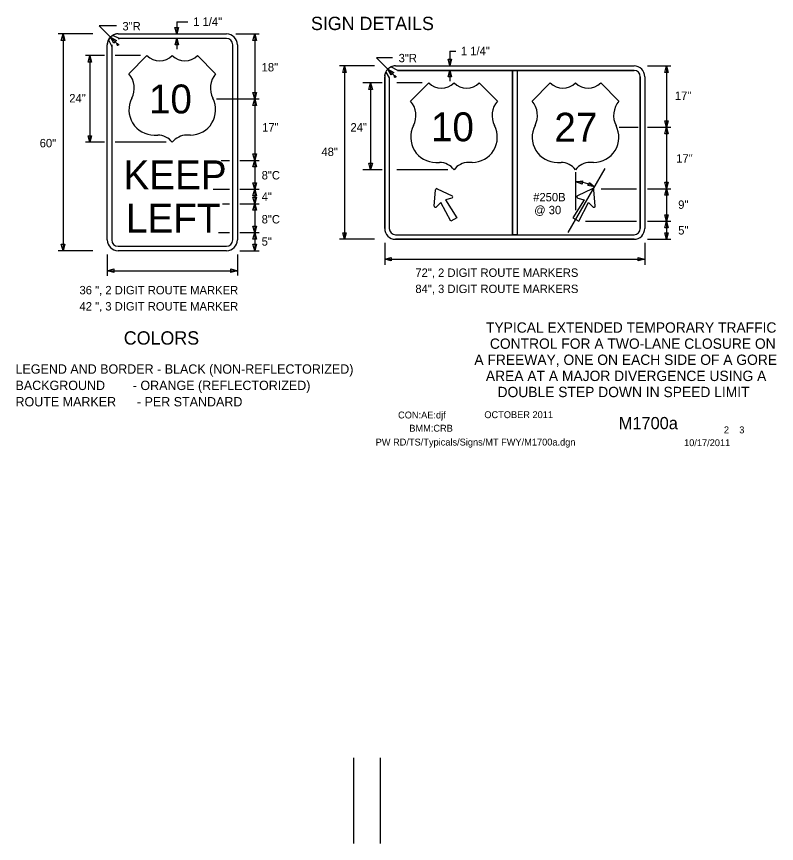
# Model space of a CAD drawing. Extents: x 16486 to 19505, y 5576 to 6998.
# Drawn here: x 17777 to 18460, y 5576 to 6320 of the extents above; entities that cross this region are included whole.
import ezdxf

# ---------------------------------------------------------------- set-up
doc = ezdxf.new("R2010")
doc.units = 0
for name, color, linetype in [('ALI_LEGAL_EX', 7, 'Continuous'), ('BORDER', 7, 'Continuous'), ('BORDER_SIGNAL_WO', 7, 'Continuous'), ('TRAFFIC_SIGNS_PR', 7, 'Continuous'), ('TYPICAL_EX', 7, 'Continuous'), ('TYPICAL_TEXT_DIMEN_PR', 7, 'Continuous')]:
    doc.layers.add(name, color=color, linetype=linetype)

msp = doc.modelspace()

# ---------------------------------------------------------------- linework, layer by layer
at = {"layer": 'ALI_LEGAL_EX'}
for p, q in [((18079.61, 5652.91), (18079.61, 5575.75)), ((18103.61, 5652.91), (18103.61, 5575.75))]:
    msp.add_line(p, q, dxfattribs=at)
at = {"layer": 'TRAFFIC_SIGNS_PR'}
for p, q in [((17860.3, 6300.32), (17859.29, 6298.82)), ((17869.08, 6299.88), (17862.99, 6302.62)), ((17867.88, 6303.94), (17965.38, 6303.94)), ((17858.13, 6118.69), (17858.13, 6294.19)), ((17859.32, 6298.74), (17862.19, 6292.7)), ((17862.19, 6294.19), (17862.19, 6118.69)), ((17965.38, 6299.88), (17867.88, 6299.88)), ((17971.06, 6118.69), (17971.06, 6294.19)), ((17975.13, 6294.19), (17975.13, 6118.69)), ((18119.35, 6271.19), (18113.12, 6274.21)), ((18117.4, 6275.24), (18331.9, 6275.24)), ((18117.4, 6275.24), (18331.9, 6275.24)), ((18119.34, 6271.18), (18222.62, 6271.18)), ((18331.9, 6271.18), (18119.34, 6271.18)), ((18222.62, 6271.18), (18222.62, 6123.31)), ((18226.68, 6271.18), (18226.68, 6123.31)), ((18226.68, 6271.18), (18331.9, 6271.18)), ((18107.65, 6265.49), (18107.65, 6128.99)), ((18107.65, 6128.99), (18107.65, 6265.49)), ((18108.57, 6269.5), (18111.71, 6264.46)), ((18111.71, 6264.44), (18111.71, 6128.99)), ((18111.71, 6264.44), (18111.71, 6128.99)), ((18337.59, 6265.49), (18337.59, 6219.74)), ((18337.59, 6128.99), (18337.59, 6265.49)), ((18341.65, 6265.49), (18341.65, 6128.99)), ((18341.65, 6265.49), (18341.65, 6128.99)), ((18337.59, 6219.74), (18337.59, 6128.99)), ((18152.25, 6149.1), (18153.4, 6163.82)), ((18154.91, 6164.69), (18168.23, 6158.33)), ((18294.38, 6164.69), (18281.07, 6158.33)), ((18297.05, 6149.1), (18295.9, 6163.82)), ((18117.4, 6123.31), (18331.9, 6123.31)), ((18117.4, 6119.24), (18331.9, 6119.24)), ((18331.9, 6119.24), (18117.4, 6119.24)), ((17867.88, 6113), (17965.38, 6113)), ((17965.38, 6108.94), (17867.88, 6108.94))]:
    msp.add_line(p, q, dxfattribs=at)
for points in [[(18119.34, 6271.18), (18119.32, 6271.19)], [(18111.71, 6264.46), (18111.71, 6264.44)], [(18168.07, 6156.36), (18162.34, 6154.78), (18172.56, 6138.61), (18167.16, 6135.49), (18158.27, 6152.43), (18154.04, 6148.26)], [(18281.23, 6156.36), (18286.96, 6154.78), (18276.74, 6138.61), (18282.14, 6135.49), (18291.03, 6152.43), (18295.26, 6148.26)]]:
    msp.add_lwpolyline(points, dxfattribs=at)
msp.add_lwpolyline([(18222.62, 6271.18), (18226.68, 6271.18), (18226.68, 6123.31), (18222.62, 6123.31)], close=True, dxfattribs=at)
for centre, radius, start, end in [((17867.88, 6294.19), 9.75, 90, 180), ((17867.29, 6296.37), 7.6, 85.58319, 124.53531), ((17965.38, 6294.19), 9.75, 0, 90), ((17865.16, 6294.78), 7.06, 145.86811, 184.82317), ((17856.73, 6293.45), 5.51, 352.24294, 7.75653), ((17868.48, 6304.31), 4.47, 262.2432, 277.7568), ((17965.38, 6294.19), 5.69, 0, 90), ((18117.4, 6265.49), 9.75, 90, 180), ((18117.4, 6265.49), 9.75, 90, 180), ((18116.72, 6268.68), 6.6, 84.11162, 123.06374), ((18118.34, 6278.36), 7.24, 277.81035, 278.05403), ((18331.9, 6265.49), 9.75, 0, 90), ((18331.9, 6265.49), 9.75, 0, 90), ((18331.9, 6265.49), 5.69, 0, 89.99421), ((18331.9, 6265.49), 5.69, 0, 90), ((18113.78, 6266.2), 6.17, 147.60925, 186.56283), ((18154.46, 6163.73), 1.06, 64.48226, 175.51774), ((18294.84, 6163.73), 1.06, 4.48226, 115.51774), ((18167.77, 6157.38), 1.06, 285.9885, 64.48226), ((18281.53, 6157.38), 1.06, 115.51774, 254.0115), ((18153.31, 6149.02), 1.06, 175.51775, 314.01151), ((18295.99, 6149.02), 1.06, 225.98849, 4.48225), ((18117.4, 6128.99), 9.75, 180, 270), ((18117.4, 6128.99), 9.75, 180, 270), ((18117.4, 6128.99), 5.69, 180, 270), ((18117.4, 6128.99), 5.69, 180, 270), ((18331.9, 6128.99), 9.75, 270, 0), ((18331.9, 6128.99), 5.69, 270, 0), ((18331.9, 6128.99), 9.75, 270, 0), ((18331.9, 6128.99), 5.69, 270, 0), ((17867.88, 6118.69), 9.75, 180, 270), ((17867.88, 6118.69), 5.69, 180, 270), ((17965.38, 6118.69), 5.69, 270, 0), ((17965.38, 6118.69), 9.75, 270, 0)]:
    msp.add_arc(centre, radius, start, end, dxfattribs=at)
at = {"layer": 'TYPICAL_EX'}
for p, q in [((17877.63, 6268.19), (17893.88, 6284.44)), ((17955.63, 6268.19), (17939.38, 6284.44)), ((18131.01, 6243.58), (18147.26, 6259.83)), ((18209.01, 6243.58), (18192.76, 6259.83)), ((18240.29, 6243.58), (18256.54, 6259.83)), ((18318.29, 6243.58), (18302.04, 6259.83)), ((17900.35, 6212.9), (17903.6, 6212.9)), ((17932.9, 6212.9), (17929.65, 6212.9)), ((18153.74, 6188.29), (18156.99, 6188.29)), ((18186.28, 6188.29), (18183.03, 6188.29)), ((18263.01, 6188.29), (18266.26, 6188.29)), ((18295.56, 6188.29), (18292.31, 6188.29))]:
    msp.add_line(p, q, dxfattribs=at)
for centre, radius, start, end in [((17905.25, 6296.28), 16.42, 226.14041, 313.85958), ((17928, 6296.28), 16.42, 226.14042, 313.85959), ((17862.23, 6255.18), 20.16, 333.09768, 40.19361), ((17971.03, 6255.18), 20.16, 139.80639, 206.90233), ((18158.64, 6271.67), 16.42, 226.14041, 313.85958), ((18181.39, 6271.67), 16.42, 226.14042, 313.85959), ((18267.91, 6271.67), 16.42, 226.14041, 313.85958), ((18290.66, 6271.67), 16.42, 226.14042, 313.85959), ((17900.4, 6235.63), 22.73, 152.6698, 269.90132), ((17932.86, 6235.63), 22.73, 270.09868, 27.3302), ((18115.61, 6230.57), 20.16, 333.09768, 40.19361), ((18224.41, 6230.57), 20.16, 139.80639, 206.90233), ((18224.89, 6230.57), 20.16, 333.09768, 40.19361), ((18333.69, 6230.57), 20.16, 139.80639, 206.90233), ((18153.78, 6211.02), 22.73, 152.6698, 269.90132), ((18186.24, 6211.02), 22.73, 270.09868, 27.3302), ((18263.06, 6211.02), 22.73, 152.6698, 269.90132), ((18295.52, 6211.02), 22.73, 270.09868, 27.3302), ((17903.65, 6196.62), 16.28, 37.1038, 90.13853), ((17929.61, 6196.62), 16.28, 89.86147, 142.8962), ((18157.03, 6172.01), 16.28, 37.1038, 90.13853), ((18182.99, 6172.01), 16.28, 89.86147, 142.8962), ((18266.31, 6172.01), 16.28, 37.1038, 90.13853), ((18292.27, 6172.01), 16.28, 89.86147, 142.8962)]:
    msp.add_arc(centre, radius, start, end, dxfattribs=at)
at = {"layer": 'TYPICAL_TEXT_DIMEN_PR'}
for p, q in [((17866.5, 6311.23), (17850.84, 6311.23)), ((17850.84, 6311.23), (17861.08, 6300.99)), ((17920.6, 6303.94), (17919.03, 6309.8)), ((17919.03, 6309.8), (17920.6, 6309.8)), ((17920.6, 6314.7), (17920.6, 6303.94)), ((17920.6, 6314.7), (17930.71, 6314.7)), ((17920.6, 6309.8), (17922.17, 6309.8)), ((17922.17, 6309.8), (17920.6, 6303.94)), ((17845.3, 6303.94), (17814, 6303.94)), ((17816.77, 6298.08), (17818.34, 6303.94)), ((17818.34, 6303.94), (17818.34, 6108.94)), ((17818.34, 6303.94), (17819.91, 6298.08)), ((17861.08, 6300.99), (17867.64, 6294.43)), ((17864.11, 6295.73), (17861.08, 6300.99)), ((17861.08, 6300.99), (17866.33, 6297.95)), ((17973.67, 6303.94), (17994.63, 6303.94)), ((17989.16, 6298.08), (17990.73, 6303.94)), ((17990.73, 6303.94), (17990.73, 6245.44)), ((17990.73, 6303.94), (17992.3, 6298.08)), ((17818.34, 6298.08), (17816.77, 6298.08)), ((17819.91, 6298.08), (17818.34, 6298.08)), ((17865.22, 6296.84), (17864.11, 6295.73)), ((17866.33, 6297.95), (17865.22, 6296.84)), ((17866.43, 6294.43), (17868.85, 6294.43)), ((17867.64, 6293.22), (17867.64, 6295.64)), ((17919.08, 6294.02), (17920.65, 6299.88)), ((17920.65, 6294.02), (17919.08, 6294.02)), ((17920.65, 6299.88), (17920.65, 6290.13)), ((17920.65, 6299.88), (17922.22, 6294.02)), ((17922.22, 6294.02), (17920.65, 6294.02)), ((17990.73, 6298.08), (17989.16, 6298.08)), ((17992.3, 6298.08), (17990.73, 6298.08)), ((18166.26, 6288.4), (18166.26, 6275.24)), ((18166.26, 6288.4), (18171.78, 6288.4)), ((17855.76, 6284.44), (17838.63, 6284.44)), ((17840.95, 6278.58), (17842.52, 6284.44)), ((17842.52, 6278.58), (17840.95, 6278.58)), ((17842.52, 6284.44), (17842.52, 6206.44)), ((17842.52, 6284.44), (17844.1, 6278.58)), ((17844.1, 6278.58), (17842.52, 6278.58)), ((17887.99, 6284.44), (17865.12, 6284.44)), ((18114.54, 6282.53), (18100.36, 6282.53)), ((18100.36, 6282.53), (18110.51, 6272.38)), ((18166.26, 6275.24), (18164.69, 6281.11)), ((18164.69, 6281.11), (18166.26, 6281.11)), ((18166.26, 6281.11), (18167.83, 6281.11)), ((18167.83, 6281.11), (18166.26, 6275.24)), ((18098.42, 6275.24), (18067.12, 6275.24)), ((18069.89, 6269.38), (18071.46, 6275.24)), ((18071.46, 6275.24), (18071.46, 6119.24)), ((18071.46, 6275.24), (18073.03, 6269.38)), ((18110.51, 6272.38), (18117.16, 6265.73)), ((18113.55, 6267.12), (18110.51, 6272.38)), ((18110.51, 6272.38), (18115.77, 6269.35)), ((18164.74, 6265.32), (18166.31, 6271.18)), ((18164.74, 6265.32), (18166.31, 6271.18)), ((18166.31, 6271.18), (18166.31, 6261.43)), ((18166.31, 6271.18), (18167.88, 6265.32)), ((18166.31, 6271.18), (18167.88, 6265.32)), ((18344.02, 6275.24), (18364.98, 6275.24)), ((18359.51, 6269.38), (18361.08, 6275.24)), ((18361.08, 6275.24), (18361.08, 6219.99)), ((18361.08, 6275.24), (18362.66, 6269.38)), ((18071.46, 6269.38), (18069.89, 6269.38)), ((18073.03, 6269.38), (18071.46, 6269.38)), ((18114.66, 6268.23), (18113.55, 6267.12)), ((18115.77, 6269.35), (18114.66, 6268.23)), ((18115.95, 6265.73), (18118.37, 6265.73)), ((18117.16, 6264.53), (18117.16, 6266.94)), ((18166.31, 6265.32), (18164.74, 6265.32)), ((18166.31, 6265.32), (18164.74, 6265.32)), ((18167.88, 6265.32), (18166.31, 6265.32)), ((18167.88, 6265.32), (18166.31, 6265.32)), ((18361.08, 6269.38), (18359.51, 6269.38)), ((18362.66, 6269.38), (18361.08, 6269.38)), ((18105.28, 6259.83), (18088.15, 6259.83)), ((18093.45, 6253.97), (18095.02, 6259.83)), ((18095.02, 6259.83), (18095.02, 6181.83)), ((18095.02, 6259.83), (18096.59, 6253.97)), ((18141.38, 6259.83), (18118.5, 6259.83)), ((17990.73, 6245.44), (17989.16, 6251.3)), ((17989.16, 6251.3), (17990.73, 6251.3)), ((17990.73, 6251.3), (17992.3, 6251.3)), ((17992.3, 6251.3), (17990.73, 6245.44)), ((18095.02, 6253.97), (18093.45, 6253.97)), ((18096.59, 6253.97), (18095.02, 6253.97)), ((17956.52, 6245.44), (17994.63, 6245.44)), ((17989.16, 6239.58), (17990.73, 6245.44)), ((17990.73, 6245.44), (17990.73, 6190.19)), ((17990.73, 6245.44), (17992.3, 6239.58)), ((17990.73, 6239.58), (17989.16, 6239.58)), ((17992.3, 6239.58), (17990.73, 6239.58)), ((18318.46, 6219.99), (18335.62, 6219.99)), ((18344.02, 6219.99), (18364.98, 6219.99)), ((18361.08, 6219.99), (18359.51, 6225.86)), ((18359.51, 6225.86), (18361.08, 6225.86)), ((18359.51, 6214.13), (18361.08, 6219.99)), ((18361.08, 6225.86), (18362.66, 6225.86)), ((18362.66, 6225.86), (18361.08, 6219.99)), ((18361.08, 6219.99), (18361.08, 6164.74)), ((18361.08, 6219.99), (18362.66, 6214.13)), ((17842.52, 6206.44), (17840.95, 6212.3)), ((17840.95, 6212.3), (17842.52, 6212.3)), ((17842.52, 6212.3), (17844.1, 6212.3)), ((17844.1, 6212.3), (17842.52, 6206.44)), ((18361.08, 6214.13), (18359.51, 6214.13)), ((18362.66, 6214.13), (18361.08, 6214.13)), ((17855.76, 6206.44), (17838.63, 6206.44)), ((17911.12, 6206.44), (17865.12, 6206.44)), ((17960.46, 6190.19), (17968.14, 6190.19)), ((17977.5, 6190.19), (17994.63, 6190.19)), ((17990.73, 6190.19), (17989.16, 6196.05)), ((17989.16, 6196.05), (17990.73, 6196.05)), ((17989.16, 6184.33), (17990.73, 6190.19)), ((17990.73, 6196.05), (17992.3, 6196.05)), ((17992.3, 6196.05), (17990.73, 6190.19)), ((17990.73, 6190.19), (17990.73, 6164.19)), ((17990.73, 6190.19), (17992.3, 6184.33)), ((17990.73, 6184.33), (17989.16, 6184.33)), ((17992.3, 6184.33), (17990.73, 6184.33)), ((18105.28, 6181.83), (18088.15, 6181.83)), ((18095.02, 6181.83), (18093.45, 6187.69)), ((18093.45, 6187.69), (18095.02, 6187.69)), ((18095.02, 6187.69), (18096.59, 6187.69)), ((18096.59, 6187.69), (18095.02, 6181.83)), ((18164.5, 6181.83), (18118.5, 6181.83)), ((18272.68, 6125.34), (18305.92, 6182.93)), ((18279.44, 6145.5), (18279.44, 6179.49)), ((17990.73, 6164.19), (17989.16, 6170.05)), ((17989.16, 6170.05), (17990.73, 6170.05)), ((17990.73, 6170.05), (17992.3, 6170.05)), ((17992.3, 6170.05), (17990.73, 6164.19)), ((18279.47, 6170.94), (18285.46, 6171.9)), ((18285.14, 6168.77), (18279.47, 6170.94)), ((18285.3, 6170.33), (18285.14, 6168.77)), ((18285.46, 6171.9), (18285.3, 6170.33)), ((18290.45, 6167.61), (18291.14, 6169.03)), ((18296.42, 6166.48), (18290.45, 6167.61)), ((18291.14, 6169.03), (18291.82, 6170.44)), ((18291.82, 6170.44), (18296.42, 6166.48)), ((18361.08, 6164.74), (18359.51, 6170.61)), ((18359.51, 6170.61), (18361.08, 6170.61)), ((18361.08, 6170.61), (18362.66, 6170.61)), ((18362.66, 6170.61), (18361.08, 6164.74)), ((17953.44, 6164.19), (17968.14, 6164.19)), ((17977.5, 6164.19), (17994.63, 6164.19)), ((17989.16, 6158.33), (17990.73, 6164.19)), ((17990.73, 6164.19), (17990.73, 6151.19)), ((17990.73, 6164.19), (17992.3, 6158.33)), ((18302.39, 6164.74), (18334.26, 6164.74)), ((18344.02, 6164.74), (18364.98, 6164.74)), ((18359.51, 6158.88), (18361.08, 6164.74)), ((18361.08, 6164.74), (18361.08, 6135.49)), ((18361.08, 6164.74), (18362.66, 6158.88)), ((17990.73, 6158.33), (17989.16, 6158.33)), ((17990.73, 6151.19), (17989.16, 6157.05)), ((17989.16, 6157.05), (17990.73, 6157.05)), ((17992.3, 6158.33), (17990.73, 6158.33)), ((17990.73, 6157.05), (17992.3, 6157.05)), ((17992.3, 6157.05), (17990.73, 6151.19)), ((18361.08, 6158.88), (18359.51, 6158.88)), ((18362.66, 6158.88), (18361.08, 6158.88)), ((17961.79, 6151.19), (17968.14, 6151.19)), ((17977.5, 6151.19), (17994.63, 6151.19)), ((17989.16, 6145.33), (17990.73, 6151.19)), ((17990.73, 6145.33), (17989.16, 6145.33)), ((17990.73, 6151.19), (17990.73, 6125.19)), ((17990.73, 6151.19), (17992.3, 6145.33)), ((17992.3, 6145.33), (17990.73, 6145.33)), ((18361.08, 6135.49), (18359.51, 6141.36)), ((18359.51, 6141.36), (18361.08, 6141.36)), ((18361.08, 6141.36), (18362.66, 6141.36)), ((18362.66, 6141.36), (18361.08, 6135.49)), ((17990.73, 6125.19), (17989.16, 6131.05)), ((17989.16, 6131.05), (17990.73, 6131.05)), ((17990.73, 6131.05), (17992.3, 6131.05)), ((17992.3, 6131.05), (17990.73, 6125.19)), ((18288.26, 6135.49), (18334.26, 6135.49)), ((18344.02, 6135.49), (18364.98, 6135.49)), ((18359.51, 6129.63), (18361.08, 6135.49)), ((18361.08, 6129.63), (18359.51, 6129.63)), ((18361.08, 6135.49), (18361.08, 6119.24)), ((18361.08, 6135.49), (18362.66, 6129.63)), ((18362.66, 6129.63), (18361.08, 6129.63)), ((17958.29, 6125.19), (17968.14, 6125.19)), ((17977.5, 6125.19), (17994.63, 6125.19)), ((17989.16, 6119.33), (17990.73, 6125.19)), ((17990.73, 6125.19), (17990.73, 6108.94)), ((17990.73, 6125.19), (17992.3, 6119.33)), ((18071.46, 6119.24), (18069.89, 6125.11)), ((18069.89, 6125.11), (18071.46, 6125.11)), ((18071.46, 6125.11), (18073.03, 6125.11)), ((18073.03, 6125.11), (18071.46, 6119.24)), ((18361.08, 6119.24), (18359.51, 6125.11)), ((18359.51, 6125.11), (18361.08, 6125.11)), ((18361.08, 6125.11), (18362.66, 6125.11)), ((18362.66, 6125.11), (18361.08, 6119.24)), ((17818.34, 6108.94), (17816.77, 6114.8)), ((17816.77, 6114.8), (17818.34, 6114.8)), ((17818.34, 6114.8), (17819.91, 6114.8)), ((17819.91, 6114.8), (17818.34, 6108.94)), ((17990.73, 6119.33), (17989.16, 6119.33)), ((17990.73, 6108.94), (17989.16, 6114.8)), ((17989.16, 6114.8), (17990.73, 6114.8)), ((17992.3, 6119.33), (17990.73, 6119.33)), ((17990.73, 6114.8), (17992.3, 6114.8)), ((17992.3, 6114.8), (17990.73, 6108.94)), ((18098.42, 6119.24), (18067.12, 6119.24)), ((18107.65, 6115.9), (18107.65, 6096.34)), ((18341.65, 6115.9), (18341.65, 6096.34)), ((18344.02, 6119.24), (18361.15, 6119.24)), ((18344.02, 6119.24), (18364.98, 6119.24)), ((18344.02, 6119.24), (18361.15, 6119.24)), ((17845.3, 6108.94), (17814, 6108.94)), ((17977.5, 6108.94), (17994.63, 6108.94)), ((17858.13, 6105.6), (17858.13, 6086.24)), ((17975.13, 6105.6), (17975.13, 6086.7)), ((18107.65, 6101.27), (18113.51, 6102.84)), ((18107.65, 6101.27), (18341.65, 6101.27)), ((18113.51, 6099.7), (18107.65, 6101.27)), ((18113.51, 6102.84), (18113.51, 6101.27)), ((18113.51, 6101.27), (18113.51, 6099.7)), ((18335.79, 6101.27), (18335.79, 6102.84)), ((18335.79, 6102.84), (18341.65, 6101.27)), ((18341.65, 6101.27), (18335.79, 6099.7)), ((18335.79, 6099.7), (18335.79, 6101.27)), ((17858.13, 6090.97), (17863.99, 6092.54)), ((17863.99, 6092.54), (17863.99, 6090.97)), ((17969.27, 6090.97), (17969.27, 6092.54)), ((17969.27, 6092.54), (17975.13, 6090.97)), ((17858.13, 6090.97), (17975.13, 6090.97)), ((17863.99, 6089.4), (17858.13, 6090.97)), ((17863.99, 6090.97), (17863.99, 6089.4)), ((17975.13, 6090.97), (17969.27, 6089.4)), ((17969.27, 6089.4), (17969.27, 6090.97))]:
    msp.add_line(p, q, dxfattribs=at)
msp.add_arc((18279.63, 6136.5), 34.39, 60.74521, 90.32117, dxfattribs=at)

# ---------------------------------------------------------------- texts
at = {"layer": 'BORDER'}
for s, p in [('TYPICAL EXTENDED TEMPORARY TRAFFIC', (18198.79, 6035.19)), ('CONTROL FOR A TWO-LANE CLOSURE ON', (18202.28, 6020.7)), ('A FREEWAY, ONE ON EACH SIDE OF A GORE', (18188.3, 6006.21)), ('AREA AT A MAJOR DIVERGENCE USING A', (18198.66, 5991.71)), ('DOUBLE STEP DOWN IN SPEED LIMIT', (18209.16, 5977.22))]:
    msp.add_text(s, height=9.3, dxfattribs=at).set_placement(p)
at = {"layer": 'BORDER_SIGNAL_WO'}
for s, height, p in [('CON:AE:djf  ', 6.2, (18119.69, 5958.06)), ('    OCTOBER 2011', 6.2, (18188.08, 5958.34)), ('    M1700a   ', 11, (18301.86, 5948.38)), ('BMM:CRB', 6.2, (18129.81, 5946.17)), (' 2    3 ', 6.2, (18410.45, 5944.7)), ('PW RD/TS/Typicals/Signs/MT FWY/M1700a.dgn      ', 6.2, (18099.55, 5933.71)), ('10/17/2011', 6.2, (18376.93, 5933.13))]:
    msp.add_text(s, height=height, dxfattribs=at).set_placement(p)
at = {"layer": 'TRAFFIC_SIGNS_PR'}
for s, p in [('10', (17895.6, 6232.44)), ('10', (18149.25, 6207.37)), ('27', (18260.26, 6207.01)), ('KEEP', (17872.73, 6164.19)), ('LEFT', (17874.97, 6125.19))]:
    msp.add_text(s, height=26, dxfattribs=at).set_placement(p)
at = {"layer": 'TYPICAL_TEXT_DIMEN_PR'}
for s, height, p in [('1 1/4"', 7.55, (17935.4, 6311.2)), ('SIGN DETAILS', 12, (18041.35, 6307.41)), ('3"R', 7.55, (17871.77, 6307.1)), ('3"R', 7.55, (18120.18, 6278.45)), ('1 1/4"', 7.55, (18176.18, 6284.82)), ('18"', 7.55, (17996.97, 6270.21)), ('24"', 7.55, (17823.97, 6242.33)), ('17"', 7.55, (18368.66, 6244.6)), ('17"', 7.55, (17997.43, 6216.16)), ('24"', 7.55, (18076.88, 6216.16)), ('60"', 7.55, (17797.37, 6201.96)), ('48"', 7.55, (18050.76, 6194.14)), ('17"', 7.55, (18369.86, 6188.24)), ('8"C', 7.55, (17997, 6173.05)), ('4" ', 7.55, (17997, 6153.79)), ('#250B', 7.55, (18241.21, 6153.34)), ('9"', 7.55, (18371.64, 6146.59)), ('@ 30', 7.55, (18242.15, 6141.78)), ('8"C', 7.55, (17997, 6133.46)), ('5"', 7.55, (18371.64, 6123.49)), ('5" ', 7.55, (17997, 6113.49)), ('72", 2 DIGIT ROUTE MARKERS', 7.55, (18135.23, 6085.41)), ('36 ", 2 DIGIT ROUTE MARKER', 7.55, (17833.18, 6069.71)), ('84", 3 DIGIT ROUTE MARKERS', 7.55, (18135.23, 6070.86)), ('42 ", 3 DIGIT ROUTE MARKER', 7.55, (17833.18, 6055.16)), ('COLORS', 12, (17873, 6024.47)), ('LEGEND AND BORDER - BLACK (NON-REFLECTORIZED)', 8.4, (17775.62, 5998.31)), ('BACKGROUND        - ORANGE (REFLECTORIZED)', 8.4, (17775.62, 5983.61)), ('ROUTE MARKER      - PER STANDARD', 8.4, (17775.62, 5968.91))]:
    msp.add_text(s, height=height, dxfattribs=at).set_placement(p)

doc.saveas('drawing.dxf')
